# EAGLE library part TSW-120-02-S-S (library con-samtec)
THROUGH-HOLE .025" SQ POST HEADER Source: Samtec TSW.pdf
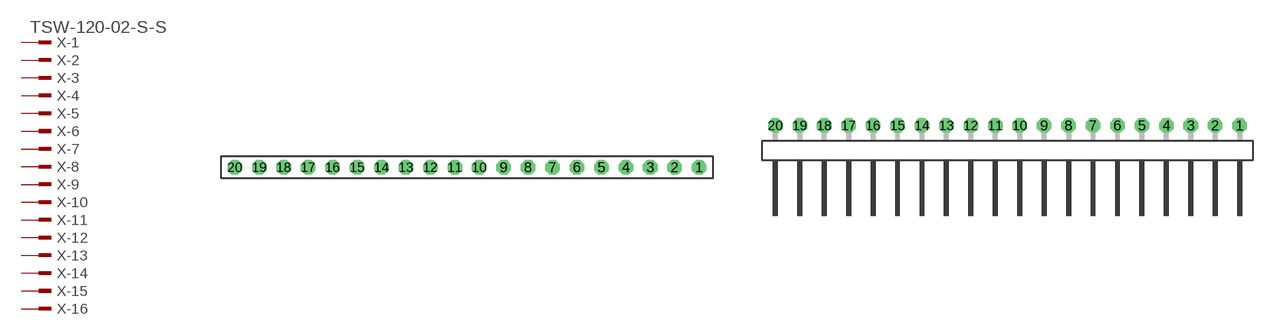
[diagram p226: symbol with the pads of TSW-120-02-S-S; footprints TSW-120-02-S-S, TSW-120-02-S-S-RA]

Designator prefix X; gates -1=MPINV -2=MPIN -3=MPIN -4=MPIN -5=MPIN -6=MPIN -7=MPIN -8=MPIN -9=MPIN -10=MPIN -11=MPIN -12=MPIN -13=MPIN -14=MPIN -15=MPIN -16=MPIN -17=MPIN -18=MPIN -19=MPIN -20=MPIN

## TSW-120-02-S-S (OC_FARNELL: unknown; OC_NEWARK: unknown)  [TSW-120-02-S-S]
1  -1:1  pas
2  -2:1  pas
3  -3:1  pas
4  -4:1  pas
5  -5:1  pas
6  -6:1  pas
7  -7:1  pas
8  -8:1  pas
9  -9:1  pas
10  -10:1  pas
11  -11:1  pas
12  -12:1  pas
13  -13:1  pas
14  -14:1  pas
15  -15:1  pas
16  -16:1  pas
17  -17:1  pas
18  -18:1  pas
19  -19:1  pas
20  -20:1  pas

## TSW-120-02-S-S-RA (OC_FARNELL: unknown; OC_NEWARK: unknown)  [TSW-120-02-S-S-RA]
Pads as for TSW-120-02-S-S

## Footprint TSW-120-02-S-S (pad centres in mm)
THROUGH-HOLE .025" SQ POST HEADER Source: Samtec TSW.pdf
drill 1 pad 1.5 octagon: 1 24.13,0; 2 21.59,0; 3 19.05,0; 4 16.51,0; 5 13.97,0; 6 11.43,0; 7 8.89,0; 8 6.35,0; 9 3.81,0; 10 1.27,0; 11 -1.27,0; 12 -3.81,0; 13 -6.35,0; 14 -8.89,0; 15 -11.43,0; 16 -13.97,0; 17 -16.51,0; 18 -19.05,0; 19 -21.59,0; 20 -24.13,0

## Footprint TSW-120-02-S-S-RA (pad centres in mm)
THROUGH-HOLE .025" SQ POST HEADER Source: Samtec TSW.pdf
drill 1 pad 1.5 octagon: 1 24.13,1.524; 2 21.59,1.524; 3 19.05,1.524; 4 16.51,1.524; 5 13.97,1.524; 6 11.43,1.524; 7 8.89,1.524; 8 6.35,1.524; 9 3.81,1.524; 10 1.27,1.524; 11 -1.27,1.524; 12 -3.81,1.524; 13 -6.35,1.524; 14 -8.89,1.524; 15 -11.43,1.524; 16 -13.97,1.524; 17 -16.51,1.524; 18 -19.05,1.524; 19 -21.59,1.524; 20 -24.13,1.524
